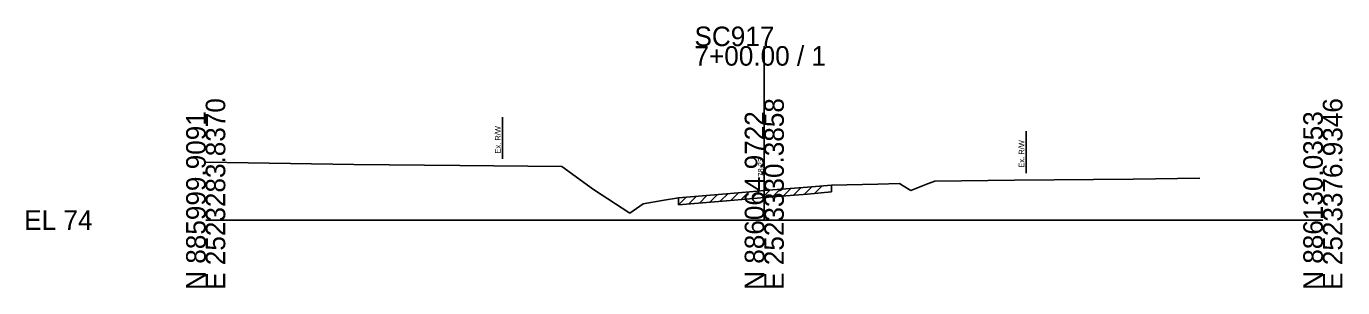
# Model space of a CAD drawing. Extents: x -26 to 218, y -10 to 12021.
# Drawn here: x -25.7 to 162.8, y 6990.3 to 7027.8 of the extents above; entities that cross this region are included whole.
import ezdxf

# ---------------------------------------------------------------- set-up
doc = ezdxf.new("R2010")
doc.units = 0
for name, color, linetype in [('RD_GPK_XS_Cell', 7, 'Continuous'), ('RD_XS_ExGround', 7, 'Continuous'), ('RD_XS_ExPaveRet', 7, 'Continuous'), ('RD_XS_ExRW', 7, 'Continuous'), ('RD_XS_TX_Elev_EX', 7, 'Continuous')]:
    doc.layers.add(name, color=color, linetype=linetype)

msp = doc.modelspace()

# ---------------------------------------------------------------- linework, layer by layer
at = {"layer": 'RD_GPK_XS_Cell'}
for p, q in [((80, 7000), (80, 7024.94)), ((0, 7000), (80, 7000)), ((80, 7000), (160, 7000))]:
    msp.add_line(p, q, dxfattribs=at)
at = {"layer": 'RD_XS_ExGround'}
for p, q in [((0, 7008.31), (21.21, 7007.98)), ((21.21, 7007.98), (36.39, 7007.84)), ((36.39, 7007.84), (51.01, 7007.67)), ((51.01, 7007.67), (55.56, 7004.38)), ((115.84, 7005.73), (132.83, 7005.87)), ((132.83, 7005.87), (142.4, 7006.02)), ((55.56, 7004.38), (60.73, 7000.97)), ((74.61, 7003.77), (79, 7004.15)), ((79, 7004.15), (80, 7004.23)), ((80, 7004.23), (86.21, 7004.74)), ((86.21, 7004.74), (89.62, 7005.03)), ((89.62, 7005.03), (96.24, 7005.14)), ((96.24, 7005.14), (99.37, 7005.24)), ((99.37, 7005.24), (99.91, 7004.89)), ((99.91, 7004.89), (101.01, 7004.22)), ((101.01, 7004.22), (103.39, 7005.18)), ((103.39, 7005.18), (104.42, 7005.58)), ((104.42, 7005.58), (115.84, 7005.73)), ((61.71, 7001.66), (62.67, 7002.35)), ((62.67, 7002.35), (65.36, 7002.8)), ((65.36, 7002.8), (67.7, 7003.19)), ((67.7, 7003.19), (74.61, 7003.77)), ((60.73, 7000.97), (61.71, 7001.66))]:
    msp.add_line(p, q, dxfattribs=at)
at = {"layer": 'RD_XS_ExPaveRet'}
for p, q in [((76.7, 7002.95), (77.79, 7004.04)), ((78.2, 7003.08), (79.29, 7004.17)), ((79.7, 7003.2), (80.79, 7004.29)), ((81.2, 7003.33), (82.29, 7004.42)), ((82.7, 7003.45), (83.79, 7004.54)), ((84.2, 7003.57), (85.29, 7004.66)), ((85.7, 7003.69), (86.79, 7004.79)), ((86.21, 7003.74), (89.62, 7004.03)), ((87.2, 7003.82), (88.29, 7004.92)), ((89.62, 7005.03), (89.62, 7004.03)), ((67.7, 7002.19), (68.79, 7003.28)), ((67.7, 7002.19), (67.7, 7003.19)), ((67.7, 7002.19), (74.61, 7002.77)), ((69.2, 7002.32), (70.29, 7003.41)), ((70.7, 7002.44), (71.79, 7003.53)), ((72.2, 7002.57), (73.29, 7003.66)), ((73.7, 7002.69), (74.79, 7003.78)), ((74.61, 7002.77), (79, 7003.15)), ((75.2, 7002.82), (76.29, 7003.91)), ((79, 7003.15), (80, 7003.23)), ((80, 7003.23), (86.21, 7003.74))]:
    msp.add_line(p, q, dxfattribs=at)
at = {"layer": 'RD_XS_ExRW'}
for p, q in [((42.5, 7014.77), (42.5, 7008.77)), ((117.5, 7012.75), (117.5, 7006.75))]:
    msp.add_line(p, q, dxfattribs=at)

# ---------------------------------------------------------------- texts
at = {"layer": 'RD_GPK_XS_Cell'}
for s, p in [('SC917', (70, 7024.94)), ('7+00.00 / 1', (70, 7022.14)), ('EL 74', (-26, 6998.6))]:
    msp.add_text(s, height=2.8, dxfattribs=at).set_placement(p)
for s, p in [('E 2523283.8370', (2.8, 6990)), ('E 2523330.3858', (82.8, 6990)), ('E 2523376.9346', (162.8, 6990)), ('N 885999.9091', (0, 6990)), ('N 886064.9722', (80, 6990)), ('N 886130.0353', (160, 6990))]:
    msp.add_text(s, height=2.8, rotation=90, dxfattribs=at).set_placement(p)
at = {"layer": 'RD_XS_ExRW'}
for p in [(42.25, 7009.55), (117.25, 7007.53)]:
    msp.add_text('Ex. R/W ', height=0.8, rotation=90, dxfattribs=at).set_placement(p)
at = {"layer": 'RD_XS_TX_Elev_EX'}
msp.add_text('78.23', height=0.8, rotation=90, dxfattribs=at).set_placement((79.9, 7006.23))

doc.saveas('drawing.dxf')
